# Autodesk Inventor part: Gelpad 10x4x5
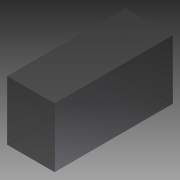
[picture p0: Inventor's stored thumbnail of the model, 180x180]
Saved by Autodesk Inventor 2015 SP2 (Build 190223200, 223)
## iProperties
Created: 2015-08
Part Number: Gelpad 10x4x5
Material: Gummi, Silikon
Document SubType Name: Modeling
Designer: ryll
Mass: 0.125 g
Surface Area: 1.6 cm^2
Volume: 0.1 cm^3
Density: 1.25 g/cm^3
Appearance: Gummi - schwarz - Version 1.1
Author: ryll
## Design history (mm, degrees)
sketch "Skizze1"
  geometry: L1 (-2, 5)-(2, 5); L2 (2, 5)-(2, -5); L3 (2, -5)-(-2, -5); L4 (-2, -5)-(-2, 5); L5 (-2.8, 0)-(2.8, 0) reference; L6 (0, 7)-(0, -7) reference; 1 further point
  constraints: 8 end point, 2 parallel, 1 horizontal, 1 perpendicular, 2 other
  dimensions: "d0" = 4 distance of L1.start L1.end; "d1" = 10 distance of L1.end L2.end
extrude "Extrusion1" new body sketch "Skizze1" distance "d2" = 5; taper "d3" = 0 deg
node "Volumenkörper1"
